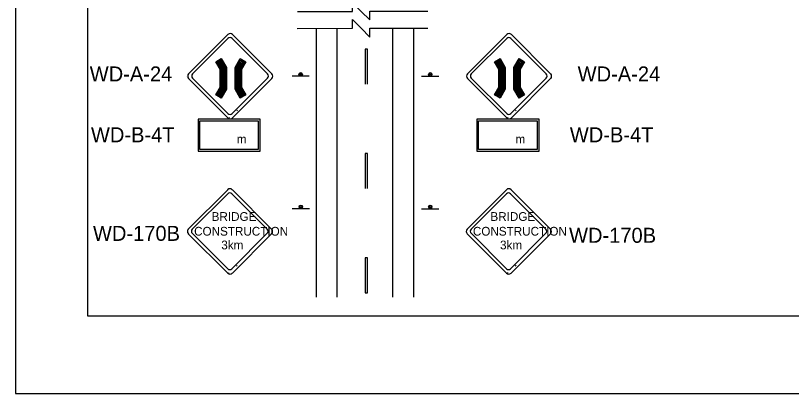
# Model space of a CAD drawing. Extents: x 2157 to 2399, y 147 to 426.
# Drawn here: x 2182.7 to 2290.7, y 147 to 199.6 of the extents above; entities that cross this region are included whole.
import ezdxf

# ---------------------------------------------------------------- set-up
doc = ezdxf.new("R2010")
doc.units = 0
for name, color, linetype in [('Level 1', 7, 'Continuous'), ('Level 10', 7, 'Continuous'), ('Level 2', 7, 'Continuous'), ('Level 20', 7, 'Continuous'), ('Level 44', 7, 'Continuous'), ('Level 60', 7, 'Continuous')]:
    doc.layers.add(name, color=color, linetype=linetype)

# ---------------------------------------------------------------- blocks, each defined once
blk = doc.blocks.new('APRNTR')
at = {"layer": 'Level 60'}
for p, q in [((-186.874, 0), (-186.874, 0)), ((-196.874, -10.809), (-196.874, -10.809))]:
    blk.add_line(p, q, dxfattribs=at)
for points in [[(19.126, 268.191), (-196.874, 268.191), (-196.874, -10.809), (19.126, -10.809)], [(0, 257.382), (-186.874, 257.382), (-186.874, 0), (0, 0)]]:
    blk.add_lwpolyline(points, close=True, dxfattribs=at)

msp = doc.modelspace()

# ---------------------------------------------------------------- linework, layer by layer
at = {"layer": 'Level 10'}
for p, q in [((2224.59, 160.39), (2224.59, 197.76)), ((2227.49, 160.39), (2227.49, 197.76)), ((2235.23, 160.39), (2235.23, 197.78)), ((2238.14, 160.39), (2238.14, 197.78)), ((2231.4, 194.85), (2231.4, 190.02)), ((2231.69, 194.85), (2231.4, 194.85)), ((2231.69, 190.02), (2231.69, 194.85)), ((2231.4, 180.34), (2231.4, 175.5)), ((2231.69, 180.34), (2231.4, 180.34)), ((2231.69, 175.5), (2231.69, 180.34)), ((2231.4, 165.83), (2231.4, 160.99)), ((2231.69, 165.83), (2231.4, 165.83)), ((2231.69, 160.99), (2231.69, 165.83)), ((2231.4, 160.99), (2231.69, 160.99))]:
    msp.add_line(p, q, dxfattribs=at)
for points in [[(2208.37, 184.9), (2216.51, 184.9), (2216.51, 180.94), (2208.37, 180.94)], [(2247.17, 184.9), (2255.31, 184.9), (2255.31, 180.94), (2247.17, 180.94)]]:
    msp.add_lwpolyline(points, close=True, dxfattribs=at)
at = {"layer": 'Level 2'}
for p, q in [((2213.63, 186.38), (2213.52, 186.28)), ((2252.42, 186.38), (2252.32, 186.28)), ((2212.51, 185.36), (2212.41, 185.26)), ((2251.31, 185.36), (2251.21, 185.26)), ((2213.59, 164.8), (2213.48, 164.69)), ((2252.38, 164.8), (2252.28, 164.69)), ((2212.47, 163.78), (2212.37, 163.68)), ((2251.27, 163.78), (2251.17, 163.68))]:
    msp.add_line(p, q, dxfattribs=at)
at = {"layer": 'Level 20'}
for points in [[(2221.95, 200.12), (2229.62, 200.13), (2229.61, 201.34), (2230.83, 200.13), (2232.04, 198.93), (2232.04, 200.14), (2240.11, 200.15)], [(2221.94, 197.75), (2229.61, 197.77), (2229.6, 198.98), (2230.82, 197.77), (2232.03, 196.56), (2232.02, 197.77), (2240.1, 197.79)]]:
    msp.add_lwpolyline(points, dxfattribs=at)
at = {"layer": 'Level 44'}
for p, q in [((2212.29, 196.9), (2206.81, 191.43)), ((2218.4, 191.43), (2212.94, 196.9)), ((2251.09, 196.9), (2245.61, 191.43)), ((2257.2, 191.43), (2251.73, 196.9)), ((2207.36, 191.43), (2212.29, 196.35)), ((2212.87, 196.35), (2217.79, 191.43)), ((2246.16, 191.43), (2251.09, 196.35)), ((2251.67, 196.35), (2256.59, 191.43)), ((2206.48, 191.11), (2206.48, 191.11)), ((2206.81, 190.78), (2212.29, 185.31)), ((2206.81, 190.78), (2206.81, 190.78)), ((2212.29, 185.92), (2207.36, 190.84)), ((2217.79, 190.84), (2212.87, 185.92)), ((2212.94, 185.31), (2218.4, 190.78)), ((2223.61, 191.1), (2221.22, 191.1)), ((2239.23, 191.1), (2241.63, 191.1)), ((2245.61, 190.78), (2251.09, 185.31)), ((2245.61, 190.78), (2245.61, 190.78)), ((2251.09, 185.92), (2246.16, 190.84)), ((2256.59, 190.84), (2251.67, 185.92)), ((2251.73, 185.31), (2257.2, 190.78)), ((2212.25, 175.32), (2206.77, 169.85)), ((2218.37, 169.85), (2212.9, 175.32)), ((2251.05, 175.32), (2245.57, 169.85)), ((2257.16, 169.85), (2251.69, 175.32)), ((2207.32, 169.85), (2212.25, 174.77)), ((2212.83, 174.77), (2217.76, 169.85)), ((2246.12, 169.85), (2251.05, 174.77)), ((2251.63, 174.77), (2256.55, 169.85)), ((2223.64, 172.67), (2221.24, 172.67)), ((2239.24, 172.67), (2241.64, 172.67)), ((2206.77, 169.2), (2212.25, 163.73)), ((2206.78, 169.2), (2206.77, 169.2)), ((2212.25, 164.33), (2207.32, 169.26)), ((2217.76, 169.26), (2212.83, 164.33)), ((2212.9, 163.73), (2218.37, 169.2)), ((2245.57, 169.2), (2251.05, 163.73)), ((2245.57, 169.2), (2245.57, 169.2)), ((2251.05, 164.33), (2246.12, 169.26)), ((2256.55, 169.26), (2251.63, 164.33)), ((2251.69, 163.73), (2257.16, 169.2))]:
    msp.add_line(p, q, dxfattribs=at)
for points in [[(2210.59, 188.52), (2211.19, 189.56), (2211.19, 192.08), (2210.59, 193.12), (2211.36, 193.57), (2212.08, 192.32), (2212.08, 189.32), (2211.36, 188.08), (2210.59, 188.52), (2210.73, 188.56), (2211.3, 189.53), (2211.3, 192.1), (2210.73, 193.08), (2211.32, 193.42), (2211.97, 192.29), (2211.97, 189.35), (2211.31, 188.22), (2210.73, 188.56), (2210.89, 188.6), (2211.41, 189.5), (2211.41, 192.14), (2210.89, 193.04), (2211.28, 193.26), (2211.86, 192.25), (2211.86, 189.38), (2211.28, 188.38), (2210.89, 188.6), (2211.03, 188.64), (2211.52, 189.47), (2211.52, 192.17), (2211.03, 193), (2211.24, 193.11), (2211.75, 192.23), (2211.75, 189.41), (2211.23, 188.52), (2211.03, 188.64), (2211.19, 188.68), (2211.29, 188.63), (2211.19, 188.68), (2211.63, 189.44), (2211.63, 192.2), (2211.19, 192.96), (2211.29, 193.01), (2211.36, 193.57)], [(2214, 188.08), (2213.28, 189.32), (2213.28, 192.32), (2214, 193.57), (2214.77, 193.12), (2214.17, 192.08), (2214.17, 189.56), (2214.77, 188.52), (2214, 188.08), (2214.04, 188.25), (2213.4, 189.35), (2213.41, 192.28), (2214.05, 193.39), (2214.59, 193.07), (2214.04, 192.11), (2214.04, 189.53), (2214.59, 188.57), (2214.04, 188.25), (2214.09, 188.42), (2213.53, 189.39), (2213.53, 192.25), (2214.09, 193.21), (2214.42, 193.02), (2213.91, 192.14), (2213.91, 189.49), (2214.42, 188.61), (2214.09, 188.42), (2214.13, 188.6), (2213.66, 189.42), (2213.66, 192.21), (2214.14, 193.04), (2214.25, 192.97), (2213.78, 192.18), (2213.79, 189.46), (2214.25, 188.66), (2214.13, 188.6), (2214.77, 188.52)], [(2249.39, 188.52), (2249.99, 189.56), (2249.99, 192.08), (2249.39, 193.12), (2250.16, 193.57), (2250.88, 192.32), (2250.88, 189.32), (2250.16, 188.08), (2249.39, 188.52), (2249.53, 188.56), (2250.09, 189.53), (2250.1, 192.1), (2249.53, 193.08), (2250.12, 193.42), (2250.77, 192.29), (2250.77, 189.35), (2250.11, 188.22), (2249.53, 188.56), (2249.69, 188.6), (2250.2, 189.5), (2250.21, 192.14), (2249.69, 193.04), (2250.08, 193.26), (2250.66, 192.25), (2250.66, 189.38), (2250.08, 188.38), (2249.69, 188.6), (2249.83, 188.64), (2250.32, 189.47), (2250.31, 192.17), (2249.83, 193), (2250.04, 193.11), (2250.55, 192.23), (2250.55, 189.41), (2250.02, 188.52), (2249.83, 188.64), (2249.99, 188.68), (2250.09, 188.63), (2249.99, 188.68), (2250.42, 189.44), (2250.43, 192.2), (2249.99, 192.96), (2250.09, 193.01), (2250.16, 193.57)], [(2252.8, 188.08), (2252.08, 189.32), (2252.08, 192.32), (2252.8, 193.57), (2253.57, 193.12), (2252.97, 192.08), (2252.97, 189.56), (2253.57, 188.52), (2252.8, 188.08), (2252.84, 188.25), (2252.2, 189.35), (2252.21, 192.28), (2252.85, 193.39), (2253.39, 193.07), (2252.84, 192.11), (2252.83, 189.53), (2253.39, 188.57), (2252.84, 188.25), (2252.89, 188.42), (2252.33, 189.39), (2252.33, 192.25), (2252.89, 193.21), (2253.22, 193.02), (2252.71, 192.14), (2252.71, 189.49), (2253.22, 188.61), (2252.89, 188.42), (2252.93, 188.6), (2252.46, 189.42), (2252.46, 192.21), (2252.94, 193.04), (2253.04, 192.97), (2252.58, 192.18), (2252.58, 189.46), (2253.04, 188.66), (2252.93, 188.6), (2253.57, 188.52)]]:
    msp.add_lwpolyline(points, dxfattribs=at)
for points in [[(2216.79, 185.13), (2208.12, 185.13), (2208.12, 180.7), (2216.79, 180.7)], [(2255.58, 185.13), (2246.92, 185.13), (2246.92, 180.7), (2255.58, 180.7)]]:
    msp.add_lwpolyline(points, close=True, dxfattribs=at)
for centre, radius in [((2222.41, 191.37), 0.24), ((2222.41, 191.37), 0.12), ((2240.44, 191.37), 0.24), ((2240.44, 191.37), 0.12), ((2222.43, 172.94), 0.24), ((2222.43, 172.94), 0.12), ((2240.44, 172.94), 0.24), ((2240.44, 172.94), 0.12)]:
    msp.add_circle(centre, radius, dxfattribs=at)
for centre, radius, start, end in [((2212.61, 196.58), 0.458, 45, 135), ((2251.41, 196.58), 0.458, 45, 135), ((2212.58, 196.06), 0.412, 45, 135), ((2251.38, 196.06), 0.412, 45, 135), ((2207.14, 191.11), 0.458, 135, 225), ((2207.65, 191.14), 0.412, 135, 225), ((2217.5, 191.14), 0.412, 315, 45), ((2218.08, 191.11), 0.458, 315, 45), ((2245.94, 191.11), 0.458, 135, 225), ((2246.45, 191.14), 0.412, 135, 225), ((2256.3, 191.14), 0.412, 315, 45), ((2256.88, 191.11), 0.458, 315, 45), ((2212.58, 186.21), 0.412, 225, 315), ((2251.38, 186.21), 0.412, 225, 315), ((2212.61, 185.63), 0.458, 225, 315), ((2251.41, 185.63), 0.458, 225, 315), ((2212.57, 175), 0.458, 45, 135), ((2251.37, 175), 0.458, 45, 135), ((2212.54, 174.48), 0.412, 45, 135), ((2251.34, 174.48), 0.412, 45, 135), ((2207.1, 169.53), 0.458, 135, 225), ((2207.61, 169.55), 0.412, 135, 225), ((2217.46, 169.55), 0.412, 315, 45), ((2218.04, 169.53), 0.458, 315, 45), ((2245.9, 169.53), 0.458, 135, 225), ((2246.41, 169.55), 0.412, 135, 225), ((2256.26, 169.55), 0.412, 315, 45), ((2256.84, 169.53), 0.458, 315, 45), ((2212.54, 164.63), 0.412, 225, 315), ((2251.34, 164.63), 0.412, 225, 315), ((2212.57, 164.05), 0.458, 225, 315), ((2251.37, 164.05), 0.458, 225, 315)]:
    msp.add_arc(centre, radius, start, end, dxfattribs=at)

# ---------------------------------------------------------------- block references
at = {"layer": 'Level 10'}
msp.add_blockref('APRNTR', (2379.59, 157.8), dxfattribs=at)

# ---------------------------------------------------------------- texts
at = {"layer": 'Level 1'}
for p in [(2193.22, 181.92), (2259.87, 181.92)]:
    msp.add_text('WD-B-4T', height=2.09, dxfattribs=at).set_placement(p)
at = {"layer": 'Level 10'}
for s, p in [('WD-A-24', (2193.05, 190.38)), ('WD-A-24', (2260.96, 190.38)), ('WD-170B', (2193.5, 168.21)), ('WD-170B', (2259.76, 167.94))]:
    msp.add_text(s, height=2.09, dxfattribs=at).set_placement(p)
at = {"layer": 'Level 44'}
for s, height, p in [('m', 1.21, (2213.51, 181.76)), ('m', 1.21, (2252.31, 181.76)), ('CONSTRUCTION', 1.2143, (2207.58, 168.94)), ('CONSTRUCTION', 1.2143, (2246.38, 168.94)), ('3km', 1.214, (2211.36, 167.03)), ('3km', 1.214, (2250.16, 167.03))]:
    msp.add_text(s, height=height, dxfattribs=at).set_placement(p)
for p in [(2210.02, 170.99), (2248.82, 170.99)]:
    msp.add_text('BRIDGE', height=1.214, rotation=360, dxfattribs=at).set_placement(p)

doc.saveas('drawing.dxf')
